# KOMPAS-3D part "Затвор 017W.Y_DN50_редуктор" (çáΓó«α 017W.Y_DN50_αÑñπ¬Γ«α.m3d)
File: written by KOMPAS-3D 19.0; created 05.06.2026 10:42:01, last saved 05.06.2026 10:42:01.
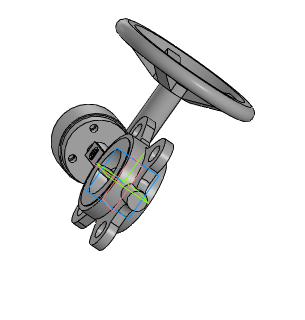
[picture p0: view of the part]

Document properties: Автор: Энергия; Полное имя файла: ..\..\..\3d для проектировщиков\x.x Тип 017W.Y(S) Затвор дисковый поворотный межфланцевый\Затвор 017W.Y(S)_DN50-DN1200_редуктор\Затвор 017W.Y_DN50_редуктор.a3d

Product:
- Part/product: Затвор 017W.Y_DN50_редуктор
    Масса: 5.35134

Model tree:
1. Операция без истории:1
